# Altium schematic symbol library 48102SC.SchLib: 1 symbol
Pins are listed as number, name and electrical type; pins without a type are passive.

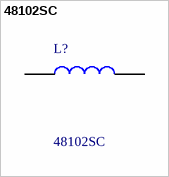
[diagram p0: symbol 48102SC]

## 48102SC
designator L?
1 mH Shielded Wirewound Inductor 520 mA 1.85Ohm Max Nonstandard, 4 Lead; Manufacturer_Name: Murata Electronics; Geometry.Height: 6mm
footprint 48102SC
pins: 1, 2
